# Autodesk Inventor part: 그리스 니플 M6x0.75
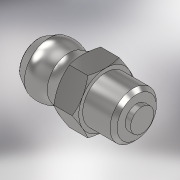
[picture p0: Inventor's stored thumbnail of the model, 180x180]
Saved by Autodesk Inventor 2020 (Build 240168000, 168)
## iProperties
Created: 2024-11
Part Number: 그리스 니플 M6x0.75
Material: 강철, 연강
Description: 윤활 니플, 원추 유형 A
Document SubType Name: Modeling
Designer: 1강의실14
Density: 7.85 g/cm^3
Appearance: 기본값
Author: jhkim
Sending System: Autodesk Inventor 2025
Preprocessor: ST-DEVELOPER v20
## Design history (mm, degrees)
feature "Solid1"
node "솔리드1"
